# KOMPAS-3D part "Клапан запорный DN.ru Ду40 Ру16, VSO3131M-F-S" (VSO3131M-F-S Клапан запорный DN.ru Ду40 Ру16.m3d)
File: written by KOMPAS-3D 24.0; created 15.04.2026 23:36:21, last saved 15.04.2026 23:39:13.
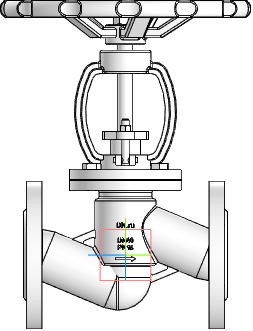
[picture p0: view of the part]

Document properties: Автор: R2D2; Полное имя файла: E:\Работа\Зайцев\VSO3131M-F-S Клапан запорный DN.ru Ду15-100 Ру16\DN40\VSO3131M-F-S Клапан запорный DN.ru Ду40 Ру16.m3d

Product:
- Part/product: Клапан запорный DN.ru Ду40 Ру16  | designation VSO3131M-F-S
    Масса: 8.25
    Раздел спецификации: Прочие изделия
    Примечание: D090-02950

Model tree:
1. Операция без истории:1

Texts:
  VSO3131M-F-S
